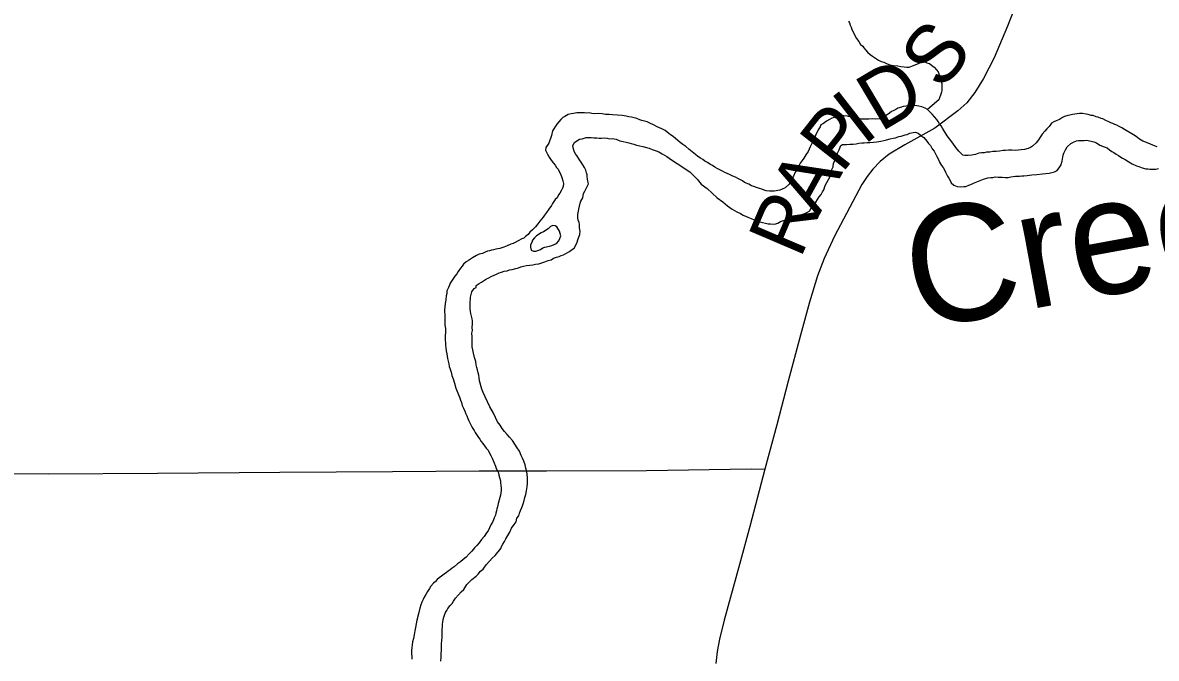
# Model space of a CAD drawing. Extents: x 0 to 34, y 0 to 22.
# Drawn here: x 4.731 to 5.838, y 18.68 to 19.302 of the extents above; entities that cross this region are included whole.
import ezdxf

# ---------------------------------------------------------------- set-up
doc = ezdxf.new("R2010")
doc.units = 0
for name, color, linetype in [('GM_X_County_Road', 7, 'Continuous'), ('GM_X_County_Road_Text', 7, 'Continuous'), ('GM_X_Major_River', 7, 'Continuous'), ('GM_X_Major_River_Text', 7, 'Continuous'), ('GM_X_Minor_River', 7, 'Continuous'), ('GM_X_Township_Road', 7, 'Continuous')]:
    doc.layers.add(name, color=color, linetype=linetype)

msp = doc.modelspace()

# ---------------------------------------------------------------- linework, layer by layer
at = {"layer": 'GM_X_County_Road'}
msp.add_lwpolyline([(5.7204, 19.3683), (5.6932, 19.298), (5.6799, 19.2672), (5.6695, 19.2471), (5.6612, 19.2333), (5.6532, 19.2231), (5.6445, 19.2153), (5.6222, 19.1986), (5.5929, 19.1821), (5.5774, 19.1731), (5.5686, 19.1659), (5.5614, 19.1583), (5.556, 19.1513), (5.5509, 19.1433), (5.524, 19.0929), (5.5141, 19.0711), (5.5075, 19.0543), (5.4998, 19.0284), (5.491, 18.9962), (5.4789, 18.9513), (5.4678, 18.9086), (5.4561, 18.8653), (5.4414, 18.8092), (5.4313, 18.7722), (5.4162, 18.7177), (5.4116, 18.6992), (5.4093, 18.687), (5.4082, 18.6752)], dxfattribs=at)
at = {"layer": 'GM_X_Major_River'}
for points in [[(5.7921, 19.2045), (5.789, 19.206), (5.7863, 19.2075), (5.7844, 19.2078), (5.7817, 19.2093), (5.7798, 19.2096), (5.7767, 19.2107), (5.7748, 19.211), (5.7718, 19.2117), (5.7699, 19.212), (5.7664, 19.2127), (5.7634, 19.2127), (5.7611, 19.2126), (5.7588, 19.2122), (5.7565, 19.2118), (5.7539, 19.2113), (5.752, 19.2109), (5.7486, 19.2097), (5.7467, 19.2089), (5.7437, 19.2069), (5.7407, 19.2057), (5.7384, 19.2045), (5.7362, 19.2033), (5.7336, 19.2002), (5.7314, 19.1979), (5.7295, 19.1956), (5.7269, 19.1925), (5.7251, 19.1898), (5.7232, 19.1871), (5.721, 19.184), (5.7176, 19.1809), (5.7154, 19.1797), (5.7131, 19.1785), (5.7097, 19.1777), (5.7063, 19.1772), (5.7036, 19.1768), (5.7006, 19.1767), (5.6972, 19.177), (5.6941, 19.177), (5.6911, 19.1765), (5.6888, 19.1765), (5.6854, 19.176), (5.682, 19.1756), (5.6786, 19.1755), (5.6759, 19.175), (5.6725, 19.175), (5.6702, 19.1745), (5.6676, 19.1745), (5.6649, 19.174), (5.6619, 19.1728), (5.66, 19.1724), (5.6581, 19.172), (5.6547, 19.1719), (5.6513, 19.1718), (5.6493, 19.1722), (5.6455, 19.1759), (5.6427, 19.1796), (5.6396, 19.1838), (5.6365, 19.1879), (5.6341, 19.1909), (5.6294, 19.1983), (5.6282, 19.2006), (5.6266, 19.2028), (5.6254, 19.2051), (5.6239, 19.207), (5.6219, 19.2096), (5.6196, 19.2122), (5.6173, 19.2144), (5.6149, 19.2167), (5.6126, 19.2181), (5.6095, 19.2192), (5.6065, 19.2199), (5.6046, 19.2202), (5.6023, 19.2206), (5.6004, 19.2205), (5.5977, 19.2205), (5.5958, 19.2204), (5.5936, 19.22), (5.5913, 19.2196), (5.5894, 19.2191), (5.586, 19.2179), (5.5841, 19.2167), (5.5815, 19.2155), (5.5796, 19.2147), (5.5777, 19.2132), (5.5736, 19.2101), (5.5706, 19.2085), (5.5679, 19.2077), (5.5645, 19.2072), (5.5611, 19.2075), (5.5577, 19.2074), (5.5546, 19.2074), (5.552, 19.2073), (5.5501, 19.2073), (5.5482, 19.2076), (5.5409, 19.2093), (5.5378, 19.21), (5.5359, 19.2104), (5.534, 19.2103), (5.5321, 19.2107), (5.5291, 19.2102)], [(5.278, 19.2135), (5.2741, 19.2134), (5.2722, 19.2134), (5.2692, 19.2129), (5.2669, 19.2125), (5.2639, 19.2117), (5.2605, 19.2097), (5.2586, 19.2089), (5.2568, 19.207), (5.2549, 19.2046), (5.2527, 19.2023), (5.2487, 19.1958), (5.2476, 19.1912), (5.2451, 19.1839), (5.2422, 19.1797), (5.2418, 19.177), (5.2438, 19.1732), (5.2454, 19.1702), (5.2474, 19.1672), (5.2497, 19.1642), (5.2513, 19.1624), (5.2525, 19.1601), (5.254, 19.1583), (5.2552, 19.156), (5.2564, 19.1537), (5.2576, 19.1504), (5.2588, 19.147), (5.2593, 19.1443), (5.2589, 19.1416), (5.2582, 19.1397), (5.2575, 19.1378), (5.2557, 19.1351), (5.2546, 19.1332), (5.2531, 19.1305), (5.2512, 19.1286), (5.2487, 19.1247), (5.2476, 19.1228), (5.245, 19.1193), (5.2427, 19.1162), (5.2409, 19.1135), (5.2394, 19.1116), (5.2361, 19.1077), (5.2342, 19.105), (5.232, 19.1019), (5.229, 19.0992), (5.2264, 19.0969), (5.2249, 19.0945), (5.2223, 19.0926), (5.2205, 19.091), (5.2186, 19.0902), (5.2152, 19.0882), (5.2122, 19.0867), (5.2103, 19.0859), (5.208, 19.0851), (5.2043, 19.0835), (5.2009, 19.0822), (5.199, 19.0814), (5.1971, 19.081), (5.1952, 19.0806), (5.1933, 19.0802), (5.191, 19.0797), (5.1891, 19.0793), (5.1872, 19.0785), (5.185, 19.0781), (5.1827, 19.0773), (5.1801, 19.0761), (5.177, 19.0753), (5.1744, 19.0741), (5.1703, 19.0717), (5.1684, 19.0705), (5.1665, 19.0693), (5.1643, 19.0678), (5.1617, 19.0654), (5.1602, 19.0635), (5.1587, 19.0616), (5.1565, 19.0585), (5.155, 19.0562), (5.1532, 19.0538), (5.1506, 19.05), (5.1487, 19.0469), (5.148, 19.045), (5.1469, 19.0427), (5.1455, 19.0396), (5.1455, 19.0369), (5.1448, 19.0347), (5.1445, 19.0308), (5.1442, 19.0289), (5.1438, 19.027), (5.1435, 19.0236), (5.1432, 19.0213), (5.1432, 19.0194), (5.1433, 19.016), (5.1434, 19.0141), (5.1434, 19.0122), (5.1435, 19.0095), (5.1435, 19.0061), (5.144, 19.0027), (5.144, 19.0004), (5.1441, 18.9985), (5.1437, 18.9963), (5.1438, 18.9936)], [(5.5291, 19.2102), (5.5261, 19.2098), (5.5238, 19.209), (5.5215, 19.2082), (5.5193, 19.207), (5.5163, 19.2054), (5.5133, 19.203), (5.5106, 19.2018), (5.5099, 19.1999), (5.5081, 19.1968), (5.507, 19.1945), (5.5059, 19.1922), (5.5052, 19.1903), (5.5044, 19.1884), (5.503, 19.1853), (5.5012, 19.1823), (5.5004, 19.1803), (5.4993, 19.178), (5.4983, 19.1757), (5.496, 19.1723), (5.4942, 19.1692), (5.4924, 19.1669), (5.4905, 19.1642), (5.4883, 19.1596), (5.4869, 19.1572), (5.4858, 19.1553), (5.4839, 19.1515), (5.4821, 19.1484), (5.481, 19.1457), (5.4799, 19.1438), (5.4758, 19.1403), (5.4728, 19.1387), (5.4705, 19.1379), (5.4652, 19.137), (5.4629, 19.137), (5.4607, 19.1369), (5.4572, 19.1372), (5.4553, 19.1379), (5.453, 19.1387), (5.4507, 19.1394), (5.448, 19.1404), (5.4453, 19.1415), (5.443, 19.1422), (5.4404, 19.1437), (5.4361, 19.1455), (5.4342, 19.147), (5.4323, 19.1481), (5.4296, 19.1492), (5.4273, 19.1506), (5.4246, 19.1517), (5.4215, 19.1532), (5.4192, 19.1543), (5.4169, 19.155), (5.4146, 19.1564), (5.4119, 19.1579), (5.4096, 19.159), (5.4073, 19.1605), (5.405, 19.1619), (5.4023, 19.1634), (5.4, 19.1649), (5.3973, 19.1663), (5.3953, 19.1678), (5.393, 19.1693), (5.3907, 19.1707), (5.3884, 19.1726), (5.3849, 19.1752), (5.3818, 19.1778), (5.3787, 19.1804), (5.376, 19.1826), (5.3733, 19.1844), (5.3663, 19.1903), (5.364, 19.1918), (5.3605, 19.1944), (5.3586, 19.1963), (5.3555, 19.1977), (5.3532, 19.1988), (5.3509, 19.1999), (5.3474, 19.2017), (5.3436, 19.2035), (5.3409, 19.2046), (5.3386, 19.2053), (5.3359, 19.206), (5.334, 19.2067), (5.3309, 19.2078), (5.3283, 19.2085), (5.3256, 19.2092), (5.3233, 19.2095), (5.3206, 19.2102), (5.3168, 19.2109), (5.3122, 19.2112), (5.3073, 19.2115), (5.3039, 19.2118), (5.3004, 19.2117), (5.297, 19.2124), (5.2936, 19.2127), (5.2901, 19.2126), (5.2871, 19.2129), (5.2844, 19.2133), (5.2818, 19.2132), (5.2799, 19.2135), (5.278, 19.2135)], [(5.8394, 19.1801), (5.8356, 19.1816), (5.8321, 19.183), (5.8294, 19.1841), (5.8271, 19.1852), (5.8252, 19.1859), (5.8221, 19.1877), (5.8186, 19.1903), (5.8163, 19.1918), (5.8074, 19.1973), (5.8047, 19.1987), (5.8021, 19.2002), (5.7998, 19.2013), (5.7978, 19.202), (5.7959, 19.2031), (5.794, 19.2038), (5.7921, 19.2045)], [(5.4499, 19.1074), (5.4537, 19.1064), (5.4568, 19.1057), (5.4594, 19.105), (5.4617, 19.105), (5.4648, 19.1047), (5.4667, 19.1051), (5.4686, 19.1055), (5.4712, 19.1071), (5.4776, 19.1092), (5.4821, 19.1104), (5.4852, 19.1112), (5.4871, 19.112), (5.4889, 19.1125), (5.4923, 19.114), (5.495, 19.1152), (5.4976, 19.1164), (5.4999, 19.1176), (5.5013, 19.1207), (5.5035, 19.1242), (5.5058, 19.1261), (5.5076, 19.1288), (5.5091, 19.1315), (5.5109, 19.1338), (5.5124, 19.1361), (5.5135, 19.1381), (5.5149, 19.1423), (5.5197, 19.1511), (5.5208, 19.1542), (5.5215, 19.158), (5.5229, 19.1607), (5.5232, 19.1641), (5.5243, 19.1664), (5.5257, 19.1714), (5.5272, 19.1748), (5.5287, 19.1772), (5.5301, 19.1814), (5.532, 19.1825), (5.5358, 19.1826), (5.5392, 19.1827), (5.5422, 19.1828), (5.5453, 19.1832), (5.5479, 19.1837), (5.5506, 19.1841), (5.5532, 19.1842), (5.5559, 19.1846), (5.5585, 19.1846), (5.562, 19.1847), (5.5654, 19.1852), (5.5692, 19.1856), (5.5722, 19.1865), (5.5749, 19.1869), (5.5783, 19.1881), (5.5813, 19.1886), (5.5836, 19.189), (5.587, 19.1902), (5.5892, 19.1906), (5.593, 19.1919), (5.5949, 19.1923), (5.5975, 19.1935), (5.6009, 19.1943), (5.6032, 19.1944), (5.6059, 19.1937), (5.6094, 19.1907), (5.6113, 19.1892), (5.6144, 19.1859), (5.616, 19.1836), (5.618, 19.1814), (5.6195, 19.1784), (5.6215, 19.1761), (5.6227, 19.1735), (5.6239, 19.1709), (5.6255, 19.1679), (5.6267, 19.1652), (5.6286, 19.1619), (5.6302, 19.16), (5.6314, 19.1577), (5.6326, 19.1555), (5.6346, 19.1517), (5.6358, 19.1495), (5.6369, 19.1472), (5.6381, 19.145), (5.6405, 19.1427), (5.6439, 19.1413), (5.6474, 19.141), (5.6504, 19.1414), (5.6523, 19.1415), (5.6553, 19.1427), (5.6572, 19.1435), (5.6598, 19.1447), (5.6696, 19.1487), (5.6738, 19.1499), (5.6768, 19.1504), (5.6787, 19.1504), (5.681, 19.1508), (5.684, 19.1505), (5.6879, 19.1506), (5.6909, 19.1503), (5.6936, 19.1503), (5.6962, 19.1508), (5.7008, 19.1516)], [(5.2445, 19.0691), (5.2472, 19.0699), (5.2494, 19.0715), (5.2524, 19.0723), (5.2551, 19.0732), (5.257, 19.074), (5.2592, 19.0748), (5.2615, 19.076), (5.2652, 19.0779), (5.2671, 19.0795), (5.2697, 19.0811), (5.2723, 19.0861), (5.2737, 19.0903), (5.2752, 19.0945), (5.2755, 19.0979), (5.275, 19.101), (5.275, 19.1044), (5.2745, 19.1063), (5.2737, 19.1085), (5.2733, 19.1108), (5.2732, 19.1142), (5.2739, 19.1173), (5.2743, 19.1192), (5.275, 19.1222), (5.2756, 19.1253), (5.2764, 19.1272), (5.2782, 19.1303), (5.2789, 19.1345), (5.2803, 19.1368), (5.2814, 19.1395), (5.2829, 19.1422), (5.2836, 19.1441), (5.2832, 19.1467), (5.2827, 19.149), (5.2823, 19.1509), (5.2823, 19.1528), (5.2819, 19.1547), (5.2811, 19.1573), (5.2799, 19.16), (5.2783, 19.1626), (5.2767, 19.1652), (5.2751, 19.1675), (5.2724, 19.1716), (5.2708, 19.1738), (5.2696, 19.1761), (5.2688, 19.1791), (5.2684, 19.1814), (5.2702, 19.1844), (5.2725, 19.186), (5.2751, 19.1876), (5.2777, 19.188), (5.2796, 19.1888), (5.2815, 19.1893), (5.2838, 19.1893), (5.2865, 19.1894), (5.2891, 19.189), (5.2918, 19.1891), (5.2941, 19.1888), (5.2964, 19.1888), (5.2994, 19.1889), (5.3021, 19.1886), (5.3044, 19.1882), (5.307, 19.1883), (5.3089, 19.188), (5.3108, 19.1876), (5.3143, 19.1862), (5.3177, 19.1855), (5.3204, 19.1848), (5.3231, 19.1841), (5.3254, 19.1834), (5.3281, 19.1827), (5.3307, 19.182), (5.3338, 19.1813), (5.3369, 19.1806), (5.3403, 19.1795), (5.343, 19.1788), (5.346, 19.1777), (5.3499, 19.1763), (5.3526, 19.1752), (5.3556, 19.1734), (5.3603, 19.1708), (5.3649, 19.1675), (5.3703, 19.1638), (5.3827, 19.1557), (5.3861, 19.1524), (5.39, 19.1487), (5.3939, 19.1438), (5.3997, 19.1394), (5.4044, 19.1349), (5.4094, 19.1305), (5.4149, 19.1264), (5.4195, 19.1227), (5.4241, 19.1194), (5.4288, 19.1168), (5.4322, 19.115), (5.4349, 19.1136), (5.4372, 19.1125), (5.4395, 19.1114), (5.4426, 19.1103), (5.4457, 19.1088), (5.4499, 19.1074)], [(5.7008, 19.1516), (5.7049, 19.1517), (5.7072, 19.1518), (5.7091, 19.1518), (5.7122, 19.1523), (5.7167, 19.1528), (5.7216, 19.1532), (5.7273, 19.1537), (5.7338, 19.1546), (5.7391, 19.1559), (5.7417, 19.1571), (5.7443, 19.1606), (5.7454, 19.1625), (5.7458, 19.1644), (5.7465, 19.1663), (5.7468, 19.1682), (5.7475, 19.172), (5.7482, 19.174), (5.7497, 19.1774), (5.7515, 19.1801), (5.7549, 19.1836), (5.7575, 19.1848), (5.7605, 19.186), (5.7624, 19.1864), (5.7658, 19.1865), (5.7681, 19.1865), (5.7704, 19.1866), (5.7773, 19.1852), (5.78, 19.1841), (5.7834, 19.1819), (5.7876, 19.1801), (5.7903, 19.1791), (5.7927, 19.1772), (5.795, 19.1757), (5.7969, 19.1746), (5.7992, 19.1732), (5.8015, 19.1717), (5.8046, 19.1695), (5.8081, 19.1677), (5.8115, 19.1655), (5.815, 19.1636), (5.8192, 19.1618), (5.8215, 19.1611), (5.8246, 19.1597), (5.8281, 19.1586), (5.83, 19.1586), (5.8322, 19.1583), (5.8349, 19.1584), (5.8379, 19.1584), (5.8406, 19.1592)], [(5.2527, 19.102), (5.2512, 19.1029), (5.2489, 19.1033), (5.2467, 19.1025), (5.2444, 19.1002), (5.2399, 19.0971), (5.2376, 19.0963), (5.2331, 19.0932), (5.2309, 19.0913), (5.229, 19.089), (5.2283, 19.0867), (5.2272, 19.0844), (5.2272, 19.0821), (5.2276, 19.0791)], [(5.2276, 19.0791), (5.2299, 19.0783), (5.2322, 19.0784), (5.2344, 19.0788), (5.2367, 19.08), (5.239, 19.0815), (5.2412, 19.0823), (5.2458, 19.0831), (5.248, 19.0839), (5.2503, 19.0847), (5.2526, 19.0859), (5.2548, 19.0882), (5.2559, 19.0905), (5.2566, 19.0931), (5.2562, 19.0954), (5.2555, 19.0977), (5.2527, 19.102)], [(5.2086, 18.8077), (5.2112, 18.8111), (5.2131, 18.8138), (5.2137, 18.8173), (5.2156, 18.8196), (5.2163, 18.8223), (5.2174, 18.8249), (5.2185, 18.8276), (5.2192, 18.8295), (5.2199, 18.8315), (5.221, 18.8345), (5.2217, 18.8376), (5.2224, 18.8406), (5.2231, 18.8441), (5.2237, 18.8479), (5.224, 18.8517), (5.224, 18.8544), (5.2243, 18.8566), (5.2239, 18.8604), (5.2234, 18.8627), (5.2226, 18.8661), (5.2218, 18.8695), (5.2205, 18.8729), (5.2193, 18.8759), (5.2181, 18.8785), (5.2165, 18.8827), (5.2142, 18.8861), (5.2118, 18.8898), (5.2095, 18.8932), (5.2067, 18.8965), (5.2044, 18.8991), (5.2017, 18.9021), (5.1993, 18.9051), (5.1973, 18.9081), (5.195, 18.9115), (5.193, 18.9156), (5.191, 18.9201), (5.1875, 18.9261), (5.1851, 18.931), (5.1827, 18.9359), (5.1807, 18.9401), (5.1795, 18.9434), (5.1774, 18.9514), (5.177, 18.9544), (5.1765, 18.9571), (5.1761, 18.9593), (5.1753, 18.9624), (5.1748, 18.9646), (5.174, 18.9673), (5.1736, 18.9703), (5.1723, 18.9745), (5.1715, 18.9786), (5.1707, 18.982), (5.1702, 18.9847), (5.1702, 18.9869), (5.1701, 18.9892), (5.1701, 18.9915), (5.17, 18.9945), (5.1699, 18.998), (5.1703, 19.0006), (5.1702, 19.0037), (5.1705, 19.0071), (5.1704, 19.0101), (5.17, 19.012), (5.1696, 19.0147), (5.1688, 19.0173), (5.1684, 19.0192), (5.1683, 19.0222), (5.1682, 19.0257), (5.1681, 19.0287), (5.1685, 19.0314), (5.1684, 19.0333), (5.1698, 19.0386), (5.1721, 19.0417), (5.1739, 19.0429), (5.1739, 19.0448), (5.1769, 19.0468), (5.1792, 19.0479), (5.184, 19.0511), (5.1859, 19.0519), (5.1893, 19.0539), (5.1916, 19.0547), (5.1938, 19.0559), (5.1965, 19.0571), (5.1987, 19.0579), (5.2014, 19.0587), (5.2044, 19.0591), (5.2067, 19.0599), (5.2093, 19.0604), (5.2127, 19.0612), (5.2154, 19.062), (5.2176, 19.0628), (5.2203, 19.0637), (5.2233, 19.0641), (5.2263, 19.0645), (5.2294, 19.065), (5.232, 19.0654), (5.2351, 19.0659), (5.2381, 19.0667), (5.2411, 19.0679), (5.2445, 19.0691)], [(5.1438, 18.9936), (5.1438, 18.9913), (5.1439, 18.9887), (5.1439, 18.9864), (5.1444, 18.9837), (5.1448, 18.9807), (5.1453, 18.978), (5.1457, 18.9758), (5.1461, 18.9735), (5.1466, 18.9709), (5.1474, 18.9682), (5.1478, 18.9656), (5.1486, 18.9629), (5.1495, 18.9599), (5.1503, 18.9569), (5.1515, 18.9535), (5.1527, 18.9493), (5.154, 18.9444), (5.1572, 18.9373), (5.158, 18.935), (5.1588, 18.9327), (5.1596, 18.9305), (5.1604, 18.9275), (5.1616, 18.9248), (5.1628, 18.9218), (5.164, 18.9192), (5.1648, 18.9173), (5.166, 18.9147), (5.1668, 18.9124), (5.168, 18.9098), (5.1696, 18.9071), (5.1708, 18.9049), (5.172, 18.903), (5.1732, 18.9011), (5.1751, 18.8981), (5.1763, 18.8963), (5.1775, 18.8944), (5.179, 18.8921), (5.1806, 18.8903), (5.1822, 18.888), (5.1837, 18.8858), (5.1857, 18.8839), (5.1865, 18.882), (5.1885, 18.8787), (5.1897, 18.876), (5.1913, 18.8719), (5.1929, 18.8681), (5.1937, 18.8659), (5.1949, 18.8636), (5.1957, 18.8617), (5.1961, 18.8594), (5.1969, 18.8572), (5.1977, 18.8538), (5.1978, 18.8519), (5.1982, 18.8492), (5.1983, 18.847), (5.1983, 18.8443), (5.198, 18.842), (5.1977, 18.8397), (5.197, 18.8374), (5.1956, 18.8317), (5.1949, 18.8283), (5.1941, 18.8263), (5.1938, 18.8244), (5.1931, 18.8221), (5.1928, 18.8202), (5.1917, 18.8175), (5.191, 18.8156), (5.1899, 18.8133), (5.1888, 18.8114), (5.1869, 18.8079), (5.1859, 18.8049), (5.184, 18.8029), (5.1818, 18.7995), (5.1792, 18.7964), (5.177, 18.7933), (5.1747, 18.7906), (5.1725, 18.7883), (5.1699, 18.7852), (5.1673, 18.7824), (5.1643, 18.7793), (5.1613, 18.777), (5.1587, 18.7747), (5.1557, 18.7727), (5.1524, 18.7699), (5.1505, 18.7684), (5.1486, 18.7668), (5.1467, 18.7656), (5.1449, 18.7641), (5.1426, 18.7625), (5.14, 18.7606), (5.1378, 18.759), (5.1359, 18.7574), (5.1344, 18.7555), (5.1322, 18.7539), (5.1296, 18.7508), (5.1285, 18.7485), (5.1266, 18.7458), (5.1248, 18.7427), (5.1233, 18.7401), (5.1222, 18.7378)], [(5.1395, 18.6777), (5.1398, 18.6815), (5.1397, 18.6849), (5.14, 18.6884), (5.1403, 18.691), (5.1403, 18.6944), (5.1406, 18.6979), (5.1409, 18.7009), (5.1409, 18.7028), (5.1408, 18.7059), (5.1407, 18.7081), (5.1411, 18.7116), (5.141, 18.7138), (5.1413, 18.7157), (5.1417, 18.7184), (5.1424, 18.7207), (5.1431, 18.7226), (5.1442, 18.7253), (5.1453, 18.7272), (5.1464, 18.7292), (5.1486, 18.7319), (5.1505, 18.7338), (5.1519, 18.7361), (5.1538, 18.7392), (5.1568, 18.7423), (5.1594, 18.7454), (5.162, 18.7477), (5.1649, 18.7524), (5.1697, 18.7574), (5.1739, 18.7605), (5.1761, 18.7625), (5.1783, 18.7656), (5.1809, 18.7675), (5.1839, 18.7718), (5.1869, 18.7753), (5.1898, 18.7784), (5.1925, 18.7807), (5.198, 18.7877), (5.1987, 18.7896), (5.2002, 18.7919), (5.2017, 18.7946), (5.2031, 18.7973), (5.205, 18.8004), (5.2068, 18.8038), (5.2086, 18.8077)], [(5.1222, 18.7378), (5.1211, 18.7351), (5.1201, 18.7328), (5.119, 18.7293), (5.1179, 18.7251), (5.1162, 18.7175), (5.1155, 18.714), (5.1148, 18.7106), (5.1141, 18.7072), (5.1135, 18.7034), (5.1128, 18.6999), (5.1117, 18.6965), (5.1114, 18.6934), (5.1111, 18.6908), (5.1107, 18.6881), (5.1108, 18.6862), (5.1108, 18.6843), (5.1112, 18.682), (5.1113, 18.6794)]]:
    msp.add_lwpolyline(points, dxfattribs=at)
at = {"layer": 'GM_X_Minor_River'}
for points in [[(5.5378, 19.3031), (5.5386, 19.3013), (5.5394, 19.299), (5.5402, 19.2971), (5.541, 19.2948), (5.5457, 19.2862), (5.5477, 19.2832), (5.5493, 19.2802), (5.5516, 19.2787), (5.5528, 19.2769), (5.5543, 19.275), (5.5563, 19.2728), (5.559, 19.2705), (5.5613, 19.2687), (5.564, 19.2668), (5.5671, 19.265), (5.5698, 19.2636), (5.5721, 19.2628), (5.5755, 19.2614), (5.5782, 19.2603), (5.5817, 19.2596), (5.5859, 19.2593), (5.5889, 19.2586), (5.592, 19.2583), (5.5946, 19.258), (5.5969, 19.2581), (5.6003, 19.2593)], [(5.6003, 19.2593), (5.6045, 19.2609), (5.609, 19.2629), (5.6116, 19.2637), (5.6143, 19.2622), (5.617, 19.2615), (5.6189, 19.2601), (5.6213, 19.2582), (5.6236, 19.2556), (5.6252, 19.2534), (5.626, 19.2515), (5.6272, 19.2481), (5.628, 19.2462), (5.6284, 19.2443), (5.6288, 19.242), (5.629, 19.2356), (5.6286, 19.2337), (5.6261, 19.226), (5.6149, 19.2167)]]:
    msp.add_lwpolyline(points, dxfattribs=at)
at = {"layer": 'GM_X_Township_Road'}
msp.add_lwpolyline([(4.4288, 18.8614), (4.4905, 18.8612), (4.5804, 18.8612), (4.6346, 18.8612), (4.7563, 18.8607), (4.8626, 18.8612), (4.9823, 18.8623), (5.0923, 18.8628), (5.1769, 18.8635), (5.2427, 18.8635), (5.3405, 18.864), (5.4426, 18.8654), (5.4561, 18.8653)], dxfattribs=at)

# ---------------------------------------------------------------- texts
at = {"layer": 'GM_X_County_Road_Text'}
for s, rotation, p in [('S', 51.0698, (5.6286, 19.234)), ('D', 30.6983, (5.569, 19.1941)), ('I', 37.9393, (5.5522, 19.1808)), ('P', 51.8129, (5.5311, 19.1532)), ('A', 61.152, (5.5083, 19.1115)), ('R', 66.8931, (5.4907, 19.0699))]:
    msp.add_text(s, height=0.0568, rotation=rotation, dxfattribs=at).set_placement(p)
at = {"layer": 'GM_X_Major_River_Text'}
msp.add_text('Creek', height=0.11371, rotation=10.388, dxfattribs=at).set_placement((5.6042, 19.0011))

doc.saveas('drawing.dxf')
